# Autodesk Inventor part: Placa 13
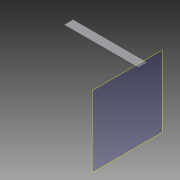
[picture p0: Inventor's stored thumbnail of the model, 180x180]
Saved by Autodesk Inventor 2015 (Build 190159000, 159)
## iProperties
Created: 2015-04
Part Number: Placa 13
Material: Generic
Document SubType Name: Modeling
Designer: suporte
Density: 1 g/cm^3
Appearance: Default
Author: suporte
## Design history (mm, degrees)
workplane "Work Plane1"
sketch "Sketch1"
  geometry: L1 (903.664, 571.131)-(912.5, 579.973) reference; L2 (912.5, -880.027)-(912.5, 919.973) reference; L3 (825, 337.473)-(812.5, 337.473) reference; L4 (900, 571.131)-(912.5, 571.131); L5 (912.5, 571.131)-(912.5, 337.473); L6 (912.5, 337.473)-(900, 337.473); L7 (900, 337.473)-(900, 571.131); L8 (825, 337.473)-(812.5, 337.473) reference; 3 further points
  constraints: 8 end point, 2 midpoint, 2 parallel, 1 horizontal, 1 horizontal alignment, 1 perpendicular, 1 point on line
  dimensions: "d0" = 12.5 distance of L5.end L6.end
extrude "Extrusion1" new body sketch "Sketch1" distance "d1" = 2100; taper "d2" = 0 deg
body "Solid1"
node "Reference1"
node "Reference2"
node "Reference3"
node "Reference4"
